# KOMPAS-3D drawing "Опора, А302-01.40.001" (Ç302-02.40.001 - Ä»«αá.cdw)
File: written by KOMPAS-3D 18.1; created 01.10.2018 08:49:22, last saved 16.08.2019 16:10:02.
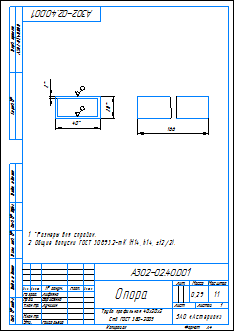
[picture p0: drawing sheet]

Sheet 1: A4, portrait

Document properties: Автор: Милов; Полное имя файла: ..\Отработка\Труба профильная 25х25х1,5-1.m3d; Материал: Ст3кп ГОСТ 380-2005; Масса: 0.291894

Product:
- Part/product: Опора  | designation А302-01.40.001
    Материал: Ст3кп ГОСТ 380-2005 (density 7850 kg/m3)
    Масса: 0.186469
    Раздел спецификации: Детали
    Форматы листов документа: A4
    Плотность: 7850
    source file: ..\А302-01.40.001 - Опора.cdw
- Part/product: Опора  | designation А302-02.40.001
    Материал: Ст3кп ГОСТ 380-2005 (density 7850 kg/m3)
    Масса: 0.291894
    Раздел спецификации: Детали
    Форматы листов документа: A4
    Плотность: 7850
    source file: А302-02.40.001 - Опора.cdw

Title block, sheet 1: Наименование: Опора; designation: А302-02.40.001; Масса: 0,29; scale: 1:1; Количество листов документа: 1; organisation: ЗАО «Астерион»; Форматы листов документа: A4; stored path: \\192.168.87.28\Konstructor_doc\Мембранные насосы\Мембранный электропривод\А302-00.00.000 - ASTRA-302 (МЭ200)\3Д ПВХ\А302-01.40.001 - Опора.cdw; Разработал: Лифлянд; Проверил: Борисенко; Т. контр.: Лучихин; Утвердил: Григорьева

Views: Проекционный вид 2, Проекционный вид 3
Referenced files in \\192.168.87.28\Konstructor_doc\Мембранные насосы\Мембранный электропривод\А302-00.00.000 - ASTRA-302 (МЭ200)\3Д ПВХ\Отработка\: Труба профильная 25х25х1,5-1.m3d
Referenced files in D:\Мембранные насосы\Мембранный электропривод\А302-00.00.000 - ASTRA-302 (МЭ200)\3Д ПВХ\Отработка\: Труба профильная 25х25х1,5-1.m3d
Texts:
  Труба профильная 40х20х2
  Ст3 ГОСТ 380-2005
Dimensions and other numbers on the sheet: 2; 40; 20; 166; 1:1; 1; 0,29

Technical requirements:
  *Размеры для справок.
  Общие допуски ГОСТ 30893.2-mK (H14, h14,  t2/2).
